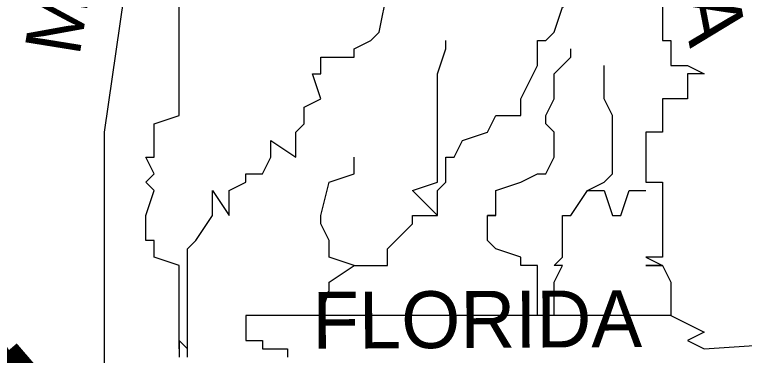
# Model space of a CAD drawing. Extents: x -12822 to 16384, y -6351 to 1913.
# Drawn here: x 65.86 to 88.88, y -4811.36 to -4800.61 of the extents above; entities that cross this region are included whole.
import ezdxf

# ---------------------------------------------------------------- set-up
doc = ezdxf.new("R2010")
doc.units = 0
doc.layers.add('great seal', color=7, linetype='Continuous')

msp = doc.modelspace()

# ---------------------------------------------------------------- linework, layer by layer
at = {"layer": 'great seal'}
for points in [[(68.693, -4813.516), (68.693, -4804.319), (71.058, -4788.028)], [(68.693, -4813.516), (68.693, -4804.319), (71.058, -4788.028)], [(68.693, -4813.516), (68.693, -4804.319), (71.058, -4788.028)], [(79.204, -4806.947), (79.204, -4806.947), (79.204, -4806.159), (79.467, -4805.896), (79.467, -4805.633), (79.467, -4805.107), (79.729, -4805.107), (79.992, -4804.582), (80.78, -4804.319), (81.043, -4803.794), (81.832, -4803.794), (81.832, -4803.268), (82.357, -4802.217), (82.357, -4801.692), (82.357, -4801.692), (82.357, -4801.429), (82.62, -4801.429), (82.883, -4801.166), (83.145, -4800.378), (83.934, -4799.852), (84.459, -4799.589), (84.459, -4799.327), (84.459, -4799.064), (83.934, -4799.064)], [(79.204, -4806.947), (79.204, -4806.947), (79.204, -4806.159), (79.467, -4805.896), (79.467, -4805.633), (79.467, -4805.107), (79.729, -4805.107), (79.992, -4804.582), (80.78, -4804.319), (81.043, -4803.794), (81.832, -4803.794), (81.832, -4803.268), (82.357, -4802.217), (82.357, -4801.692), (82.357, -4801.692), (82.357, -4801.429), (82.62, -4801.429), (82.883, -4801.166), (83.145, -4800.378), (83.934, -4799.852), (84.459, -4799.589), (84.459, -4799.327), (84.459, -4799.064), (83.934, -4799.064)], [(79.204, -4806.947), (79.204, -4806.947), (79.204, -4806.159), (79.467, -4805.896), (79.467, -4805.633), (79.467, -4805.107), (79.729, -4805.107), (79.992, -4804.582), (80.78, -4804.319), (81.043, -4803.794), (81.832, -4803.794), (81.832, -4803.268), (82.357, -4802.217), (82.357, -4801.692), (82.357, -4801.692), (82.357, -4801.429), (82.62, -4801.429), (82.883, -4801.166), (83.145, -4800.378), (83.934, -4799.852), (84.459, -4799.589), (84.459, -4799.327), (84.459, -4799.064), (83.934, -4799.064)], [(71.321, -4811.151), (71.321, -4810.888), (71.321, -4810.363), (71.321, -4810.363), (71.321, -4809.312), (71.321, -4809.049), (71.321, -4808.523), (71.321, -4808.523), (71.321, -4808.261), (71.321, -4807.998), (71.584, -4807.735), (72.109, -4806.947), (72.109, -4806.159), (72.635, -4806.947), (72.635, -4806.159), (73.16, -4805.896), (73.16, -4805.633), (73.686, -4805.633), (73.949, -4805.107), (73.949, -4804.582), (74.737, -4805.107), (74.737, -4804.319), (75, -4804.056), (75, -4803.794), (75, -4803.531), (75.525, -4803.268), (75.262, -4802.48), (75.525, -4802.48), (75.525, -4801.954), (76.576, -4801.954), (76.576, -4801.692), (76.576, -4801.692), (77.102, -4801.429), (77.365, -4801.166), (77.627, -4799.852)], [(71.321, -4811.151), (71.321, -4810.888), (71.321, -4810.363), (71.321, -4810.363), (71.321, -4809.312), (71.321, -4809.049), (71.321, -4808.523), (71.321, -4808.523), (71.321, -4808.261), (71.321, -4807.998), (71.584, -4807.735), (72.109, -4806.947), (72.109, -4806.159), (72.635, -4806.947), (72.635, -4806.159), (73.16, -4805.896), (73.16, -4805.633), (73.686, -4805.633), (73.949, -4805.107), (73.949, -4804.582), (74.737, -4805.107), (74.737, -4804.319), (75, -4804.056), (75, -4803.794), (75, -4803.531), (75.525, -4803.268), (75.262, -4802.48), (75.525, -4802.48), (75.525, -4801.954), (76.576, -4801.954), (76.576, -4801.692), (76.576, -4801.692), (77.102, -4801.429), (77.365, -4801.166), (77.627, -4799.852)], [(71.321, -4811.151), (71.321, -4810.888), (71.321, -4810.363), (71.321, -4810.363), (71.321, -4809.312), (71.321, -4809.049), (71.321, -4808.523), (71.321, -4808.523), (71.321, -4808.261), (71.321, -4807.998), (71.584, -4807.735), (72.109, -4806.947), (72.109, -4806.159), (72.635, -4806.947), (72.635, -4806.159), (73.16, -4805.896), (73.16, -4805.633), (73.686, -4805.633), (73.949, -4805.107), (73.949, -4804.582), (74.737, -4805.107), (74.737, -4804.319), (75, -4804.056), (75, -4803.794), (75, -4803.531), (75.525, -4803.268), (75.262, -4802.48), (75.525, -4802.48), (75.525, -4801.954), (76.576, -4801.954), (76.576, -4801.692), (76.576, -4801.692), (77.102, -4801.429), (77.365, -4801.166), (77.627, -4799.852)], [(71.058, -4811.151), (71.058, -4810.888), (71.058, -4810.363), (71.058, -4810.363), (71.058, -4810.1), (71.058, -4810.1), (71.058, -4809.049), (71.058, -4808.523), (71.058, -4808.523), (70.27, -4808.261), (70.27, -4807.998), (70.27, -4807.735), (70.007, -4807.735), (70.007, -4806.947), (70.007, -4806.947), (70.27, -4806.159), (70.007, -4805.896), (70.27, -4805.633), (70.007, -4805.107), (70.007, -4805.107), (70.007, -4805.107), (70.27, -4805.107), (70.27, -4804.319), (70.27, -4804.319), (70.27, -4804.056), (71.058, -4803.794), (71.058, -4803.531), (71.058, -4803.268), (71.058, -4802.48), (71.058, -4802.217), (71.058, -4801.692), (71.058, -4801.692), (71.058, -4801.429), (71.058, -4800.378)], [(71.058, -4811.151), (71.058, -4810.888), (71.058, -4810.363), (71.058, -4810.363), (71.058, -4810.1), (71.058, -4810.1), (71.058, -4809.049), (71.058, -4808.523), (71.058, -4808.523), (70.27, -4808.261), (70.27, -4807.998), (70.27, -4807.735), (70.007, -4807.735), (70.007, -4806.947), (70.007, -4806.947), (70.27, -4806.159), (70.007, -4805.896), (70.27, -4805.633), (70.007, -4805.107), (70.007, -4805.107), (70.007, -4805.107), (70.27, -4805.107), (70.27, -4804.319), (70.27, -4804.319), (70.27, -4804.056), (71.058, -4803.794), (71.058, -4803.531), (71.058, -4803.268), (71.058, -4802.48), (71.058, -4802.217), (71.058, -4801.692), (71.058, -4801.692), (71.058, -4801.429), (71.058, -4800.378)], [(71.058, -4811.151), (71.058, -4810.888), (71.058, -4810.363), (71.058, -4810.363), (71.058, -4810.1), (71.058, -4810.1), (71.058, -4809.049), (71.058, -4808.523), (71.058, -4808.523), (70.27, -4808.261), (70.27, -4807.998), (70.27, -4807.735), (70.007, -4807.735), (70.007, -4806.947), (70.007, -4806.947), (70.27, -4806.159), (70.007, -4805.896), (70.27, -4805.633), (70.007, -4805.107), (70.007, -4805.107), (70.007, -4805.107), (70.27, -4805.107), (70.27, -4804.319), (70.27, -4804.319), (70.27, -4804.056), (71.058, -4803.794), (71.058, -4803.531), (71.058, -4803.268), (71.058, -4802.48), (71.058, -4802.217), (71.058, -4801.692), (71.058, -4801.692), (71.058, -4801.429), (71.058, -4800.378)], [(86.299, -4800.378), (86.299, -4801.166), (86.299, -4801.429), (86.561, -4801.429), (86.561, -4801.692), (86.561, -4801.692), (86.561, -4801.954), (86.561, -4802.217), (87.087, -4802.217), (87.612, -4802.48), (87.087, -4802.48), (87.087, -4803.268), (87.087, -4803.268), (86.561, -4803.268), (86.561, -4803.268), (86.561, -4803.268), (86.561, -4803.268), (86.299, -4803.268), (86.299, -4803.268), (86.299, -4803.268), (86.299, -4803.531), (86.299, -4803.794), (86.299, -4803.794), (86.299, -4803.794), (86.299, -4803.794), (86.299, -4803.794), (86.299, -4804.056), (86.299, -4804.056), (86.299, -4804.056), (86.299, -4804.319), (86.299, -4804.319), (85.773, -4804.319), (85.773, -4804.319), (85.773, -4804.319), (85.773, -4804.582), (85.773, -4804.582), (85.773, -4805.107), (85.773, -4805.107), (85.773, -4805.107), (85.773, -4805.107), (85.773, -4805.107), (85.773, -4805.107), (85.773, -4805.107), (85.773, -4805.633), (85.773, -4805.633), (85.773, -4805.633), (85.773, -4805.633), (85.773, -4805.633), (85.773, -4805.633), (85.773, -4805.896), (86.299, -4805.896), (86.299, -4806.159), (86.299, -4806.159), (86.299, -4806.159), (86.299, -4806.947), (86.299, -4806.947), (86.299, -4806.947), (86.299, -4806.947), (86.299, -4806.947), (86.299, -4806.947), (86.299, -4807.21), (86.299, -4807.735), (86.299, -4807.735), (86.299, -4807.735), (86.299, -4807.998), (86.299, -4807.998), (86.299, -4808.261), (86.299, -4808.261), (85.773, -4808.261), (85.773, -4808.261), (85.773, -4808.261), (85.773, -4808.261), (86.299, -4808.523), (86.299, -4808.523), (85.773, -4808.523), (86.299, -4808.523), (86.299, -4808.523), (86.299, -4808.523), (86.561, -4809.049), (86.561, -4809.049), (86.561, -4809.312), (86.561, -4809.312), (86.561, -4810.1), (73.16, -4810.1), (73.16, -4810.363), (73.16, -4810.363)], [(86.299, -4800.378), (86.299, -4801.166), (86.299, -4801.429), (86.561, -4801.429), (86.561, -4801.692), (86.561, -4801.692), (86.561, -4801.954), (86.561, -4802.217), (87.087, -4802.217), (87.612, -4802.48), (87.087, -4802.48), (87.087, -4803.268), (87.087, -4803.268), (86.561, -4803.268), (86.561, -4803.268), (86.561, -4803.268), (86.561, -4803.268), (86.299, -4803.268), (86.299, -4803.268), (86.299, -4803.268), (86.299, -4803.531), (86.299, -4803.794), (86.299, -4803.794), (86.299, -4803.794), (86.299, -4803.794), (86.299, -4803.794), (86.299, -4804.056), (86.299, -4804.056), (86.299, -4804.056), (86.299, -4804.319), (86.299, -4804.319), (85.773, -4804.319), (85.773, -4804.319), (85.773, -4804.319), (85.773, -4804.582), (85.773, -4804.582), (85.773, -4805.107), (85.773, -4805.107), (85.773, -4805.107), (85.773, -4805.107), (85.773, -4805.107), (85.773, -4805.107), (85.773, -4805.107), (85.773, -4805.633), (85.773, -4805.633), (85.773, -4805.633), (85.773, -4805.633), (85.773, -4805.633), (85.773, -4805.633), (85.773, -4805.896), (86.299, -4805.896), (86.299, -4806.159), (86.299, -4806.159), (86.299, -4806.159), (86.299, -4806.947), (86.299, -4806.947), (86.299, -4806.947), (86.299, -4806.947), (86.299, -4806.947), (86.299, -4806.947), (86.299, -4807.21), (86.299, -4807.735), (86.299, -4807.735), (86.299, -4807.735), (86.299, -4807.998), (86.299, -4807.998), (86.299, -4808.261), (86.299, -4808.261), (85.773, -4808.261), (85.773, -4808.261), (85.773, -4808.261), (85.773, -4808.261), (86.299, -4808.523), (86.299, -4808.523), (85.773, -4808.523), (86.299, -4808.523), (86.299, -4808.523), (86.299, -4808.523), (86.561, -4809.049), (86.561, -4809.049), (86.561, -4809.312), (86.561, -4809.312), (86.561, -4810.1), (73.16, -4810.1), (73.16, -4810.363), (73.16, -4810.363)], [(86.299, -4800.378), (86.299, -4801.166), (86.299, -4801.429), (86.561, -4801.429), (86.561, -4801.692), (86.561, -4801.692), (86.561, -4801.954), (86.561, -4802.217), (87.087, -4802.217), (87.612, -4802.48), (87.087, -4802.48), (87.087, -4803.268), (87.087, -4803.268), (86.561, -4803.268), (86.561, -4803.268), (86.561, -4803.268), (86.561, -4803.268), (86.299, -4803.268), (86.299, -4803.268), (86.299, -4803.268), (86.299, -4803.531), (86.299, -4803.794), (86.299, -4803.794), (86.299, -4803.794), (86.299, -4803.794), (86.299, -4803.794), (86.299, -4804.056), (86.299, -4804.056), (86.299, -4804.056), (86.299, -4804.319), (86.299, -4804.319), (85.773, -4804.319), (85.773, -4804.319), (85.773, -4804.319), (85.773, -4804.582), (85.773, -4804.582), (85.773, -4805.107), (85.773, -4805.107), (85.773, -4805.107), (85.773, -4805.107), (85.773, -4805.107), (85.773, -4805.107), (85.773, -4805.107), (85.773, -4805.633), (85.773, -4805.633), (85.773, -4805.633), (85.773, -4805.633), (85.773, -4805.633), (85.773, -4805.633), (85.773, -4805.896), (86.299, -4805.896), (86.299, -4806.159), (86.299, -4806.159), (86.299, -4806.159), (86.299, -4806.947), (86.299, -4806.947), (86.299, -4806.947), (86.299, -4806.947), (86.299, -4806.947), (86.299, -4806.947), (86.299, -4807.21), (86.299, -4807.735), (86.299, -4807.735), (86.299, -4807.735), (86.299, -4807.998), (86.299, -4807.998), (86.299, -4808.261), (86.299, -4808.261), (85.773, -4808.261), (85.773, -4808.261), (85.773, -4808.261), (85.773, -4808.261), (86.299, -4808.523), (86.299, -4808.523), (85.773, -4808.523), (86.299, -4808.523), (86.299, -4808.523), (86.299, -4808.523), (86.561, -4809.049), (86.561, -4809.049), (86.561, -4809.312), (86.561, -4809.312), (86.561, -4810.1), (73.16, -4810.1), (73.16, -4810.363), (73.16, -4810.363)], [(76.576, -4808.523), (76.576, -4808.523), (77.102, -4808.523), (77.365, -4808.523), (77.627, -4808.523), (77.627, -4808.261), (77.627, -4807.998), (77.89, -4807.735), (78.416, -4807.21), (78.416, -4806.947), (79.204, -4806.947), (79.204, -4806.947), (78.416, -4806.159), (79.204, -4805.896), (79.204, -4805.633), (79.204, -4805.107), (79.204, -4804.582), (79.204, -4804.319), (79.204, -4803.794), (79.204, -4803.794), (79.204, -4803.268), (79.204, -4802.48), (79.467, -4801.692), (79.467, -4801.692), (79.467, -4801.429)], [(76.576, -4808.523), (76.576, -4808.523), (77.102, -4808.523), (77.365, -4808.523), (77.627, -4808.523), (77.627, -4808.261), (77.627, -4807.998), (77.89, -4807.735), (78.416, -4807.21), (78.416, -4806.947), (79.204, -4806.947), (79.204, -4806.947), (78.416, -4806.159), (79.204, -4805.896), (79.204, -4805.633), (79.204, -4805.107), (79.204, -4804.582), (79.204, -4804.319), (79.204, -4803.794), (79.204, -4803.794), (79.204, -4803.268), (79.204, -4802.48), (79.467, -4801.692), (79.467, -4801.692), (79.467, -4801.429)], [(76.576, -4808.523), (76.576, -4808.523), (77.102, -4808.523), (77.365, -4808.523), (77.627, -4808.523), (77.627, -4808.261), (77.627, -4807.998), (77.89, -4807.735), (78.416, -4807.21), (78.416, -4806.947), (79.204, -4806.947), (79.204, -4806.947), (78.416, -4806.159), (79.204, -4805.896), (79.204, -4805.633), (79.204, -4805.107), (79.204, -4804.582), (79.204, -4804.319), (79.204, -4803.794), (79.204, -4803.794), (79.204, -4803.268), (79.204, -4802.48), (79.467, -4801.692), (79.467, -4801.692), (79.467, -4801.429)], [(82.357, -4810.1), (82.357, -4809.312), (82.357, -4809.049), (82.357, -4808.523), (82.357, -4808.523), (81.832, -4808.523), (81.832, -4808.261), (81.043, -4807.998), (80.78, -4807.735), (80.78, -4807.21), (80.78, -4806.947), (81.043, -4806.947), (80.78, -4806.947), (81.043, -4806.947), (81.043, -4806.159), (81.832, -4805.896), (82.357, -4805.633), (82.357, -4805.633), (82.62, -4805.633), (82.883, -4805.107), (82.883, -4805.107), (82.883, -4804.582), (82.883, -4804.319), (82.883, -4804.319), (82.62, -4804.056), (82.62, -4803.794), (82.883, -4803.268), (82.883, -4802.48), (83.145, -4802.217), (83.408, -4801.954), (83.408, -4801.692)], [(82.357, -4810.1), (82.357, -4809.312), (82.357, -4809.049), (82.357, -4808.523), (82.357, -4808.523), (81.832, -4808.523), (81.832, -4808.261), (81.043, -4807.998), (80.78, -4807.735), (80.78, -4807.21), (80.78, -4806.947), (81.043, -4806.947), (80.78, -4806.947), (81.043, -4806.947), (81.043, -4806.159), (81.832, -4805.896), (82.357, -4805.633), (82.357, -4805.633), (82.62, -4805.633), (82.883, -4805.107), (82.883, -4805.107), (82.883, -4804.582), (82.883, -4804.319), (82.883, -4804.319), (82.62, -4804.056), (82.62, -4803.794), (82.883, -4803.268), (82.883, -4802.48), (83.145, -4802.217), (83.408, -4801.954), (83.408, -4801.692)], [(82.357, -4810.1), (82.357, -4809.312), (82.357, -4809.049), (82.357, -4808.523), (82.357, -4808.523), (81.832, -4808.523), (81.832, -4808.261), (81.043, -4807.998), (80.78, -4807.735), (80.78, -4807.21), (80.78, -4806.947), (81.043, -4806.947), (80.78, -4806.947), (81.043, -4806.947), (81.043, -4806.159), (81.832, -4805.896), (82.357, -4805.633), (82.357, -4805.633), (82.62, -4805.633), (82.883, -4805.107), (82.883, -4805.107), (82.883, -4804.582), (82.883, -4804.319), (82.883, -4804.319), (82.62, -4804.056), (82.62, -4803.794), (82.883, -4803.268), (82.883, -4802.48), (83.145, -4802.217), (83.408, -4801.954), (83.408, -4801.692)], [(83.934, -4806.159), (83.934, -4806.159), (84.459, -4805.896), (84.722, -4805.633), (84.722, -4805.633), (84.722, -4805.107), (84.722, -4804.582), (84.722, -4804.319), (84.722, -4804.056), (84.722, -4803.794), (84.459, -4803.268), (84.459, -4803.268), (84.459, -4802.217)], [(83.934, -4806.159), (83.934, -4806.159), (84.459, -4805.896), (84.722, -4805.633), (84.722, -4805.633), (84.722, -4805.107), (84.722, -4804.582), (84.722, -4804.319), (84.722, -4804.056), (84.722, -4803.794), (84.459, -4803.268), (84.459, -4803.268), (84.459, -4802.217)], [(83.934, -4806.159), (83.934, -4806.159), (84.459, -4805.896), (84.722, -4805.633), (84.722, -4805.633), (84.722, -4805.107), (84.722, -4804.582), (84.722, -4804.319), (84.722, -4804.056), (84.722, -4803.794), (84.459, -4803.268), (84.459, -4803.268), (84.459, -4802.217)], [(75.525, -4810.1), (75.788, -4809.312), (75.788, -4809.049), (76.576, -4808.523), (76.576, -4808.523), (76.576, -4808.523), (75.788, -4808.261), (75.788, -4807.998), (75.788, -4807.735), (75.525, -4807.21), (75.525, -4806.947), (75.525, -4806.947), (75.788, -4805.896), (76.576, -4805.633), (76.576, -4805.107)], [(75.525, -4810.1), (75.788, -4809.312), (75.788, -4809.049), (76.576, -4808.523), (76.576, -4808.523), (76.576, -4808.523), (75.788, -4808.261), (75.788, -4807.998), (75.788, -4807.735), (75.525, -4807.21), (75.525, -4806.947), (75.525, -4806.947), (75.788, -4805.896), (76.576, -4805.633), (76.576, -4805.107)], [(75.525, -4810.1), (75.788, -4809.312), (75.788, -4809.049), (76.576, -4808.523), (76.576, -4808.523), (76.576, -4808.523), (75.788, -4808.261), (75.788, -4807.998), (75.788, -4807.735), (75.525, -4807.21), (75.525, -4806.947), (75.525, -4806.947), (75.788, -4805.896), (76.576, -4805.633), (76.576, -4805.107)], [(82.883, -4810.1), (82.883, -4809.312), (82.883, -4809.312), (82.883, -4809.049), (83.145, -4808.523), (82.883, -4808.523), (83.145, -4808.261), (83.145, -4807.998), (83.145, -4807.735), (83.145, -4807.735), (83.145, -4807.21), (83.145, -4806.947), (83.408, -4806.947), (83.934, -4806.159), (84.459, -4806.159), (84.722, -4806.947), (84.985, -4806.947), (85.247, -4806.159), (85.51, -4806.159), (85.773, -4806.159)], [(82.883, -4810.1), (82.883, -4809.312), (82.883, -4809.312), (82.883, -4809.049), (83.145, -4808.523), (82.883, -4808.523), (83.145, -4808.261), (83.145, -4807.998), (83.145, -4807.735), (83.145, -4807.735), (83.145, -4807.21), (83.145, -4806.947), (83.408, -4806.947), (83.934, -4806.159), (84.459, -4806.159), (84.722, -4806.947), (84.985, -4806.947), (85.247, -4806.159), (85.51, -4806.159), (85.773, -4806.159)], [(82.883, -4810.1), (82.883, -4809.312), (82.883, -4809.312), (82.883, -4809.049), (83.145, -4808.523), (82.883, -4808.523), (83.145, -4808.261), (83.145, -4807.998), (83.145, -4807.735), (83.145, -4807.735), (83.145, -4807.21), (83.145, -4806.947), (83.408, -4806.947), (83.934, -4806.159), (84.459, -4806.159), (84.722, -4806.947), (84.985, -4806.947), (85.247, -4806.159), (85.51, -4806.159), (85.773, -4806.159)], [(86.561, -4810.1), (87.087, -4810.363), (87.087, -4810.363), (87.612, -4810.626), (87.087, -4810.888), (87.612, -4811.151), (91.554, -4810.888)], [(86.561, -4810.1), (87.087, -4810.363), (87.087, -4810.363), (87.612, -4810.626), (87.087, -4810.888), (87.612, -4811.151), (91.554, -4810.888)], [(86.561, -4810.1), (87.087, -4810.363), (87.087, -4810.363), (87.612, -4810.626), (87.087, -4810.888), (87.612, -4811.151), (91.554, -4810.888)], [(73.16, -4810.363), (73.16, -4810.626), (73.16, -4810.626), (73.16, -4810.888), (73.16, -4810.888), (73.686, -4810.888), (73.686, -4810.888), (73.686, -4811.151), (73.949, -4811.151), (73.949, -4811.151), (73.949, -4811.151), (74.474, -4811.151), (74.474, -4811.151), (74.474, -4811.151), (74.474, -4811.414)], [(73.16, -4810.363), (73.16, -4810.626), (73.16, -4810.626), (73.16, -4810.888), (73.16, -4810.888), (73.686, -4810.888), (73.686, -4810.888), (73.686, -4811.151), (73.949, -4811.151), (73.949, -4811.151), (73.949, -4811.151), (74.474, -4811.151), (74.474, -4811.151), (74.474, -4811.151), (74.474, -4811.414)], [(73.16, -4810.363), (73.16, -4810.626), (73.16, -4810.626), (73.16, -4810.888), (73.16, -4810.888), (73.686, -4810.888), (73.686, -4810.888), (73.686, -4811.151), (73.949, -4811.151), (73.949, -4811.151), (73.949, -4811.151), (74.474, -4811.151), (74.474, -4811.151), (74.474, -4811.151), (74.474, -4811.414)], [(71.321, -4811.414), (71.321, -4811.151), (71.321, -4811.151), (71.321, -4811.151), (71.321, -4811.151), (71.321, -4811.151), (71.321, -4811.151), (71.321, -4811.151), (71.058, -4810.888)], [(71.058, -4810.888), (71.058, -4810.888), (71.058, -4811.151), (71.058, -4811.151), (71.058, -4811.151), (71.058, -4811.151), (71.058, -4811.151), (71.058, -4811.151), (71.058, -4811.414)], [(71.321, -4811.414), (71.321, -4811.151), (71.321, -4811.151), (71.321, -4811.151), (71.321, -4811.151), (71.321, -4811.151), (71.321, -4811.151), (71.321, -4811.151), (71.058, -4810.888)], [(71.058, -4810.888), (71.058, -4810.888), (71.058, -4811.151), (71.058, -4811.151), (71.058, -4811.151), (71.058, -4811.151), (71.058, -4811.151), (71.058, -4811.151), (71.058, -4811.414)], [(71.321, -4811.414), (71.321, -4811.151), (71.321, -4811.151), (71.321, -4811.151), (71.321, -4811.151), (71.321, -4811.151), (71.321, -4811.151), (71.321, -4811.151), (71.058, -4810.888)], [(71.058, -4810.888), (71.058, -4810.888), (71.058, -4811.151), (71.058, -4811.151), (71.058, -4811.151), (71.058, -4811.151), (71.058, -4811.151), (71.058, -4811.151), (71.058, -4811.414)], [(71.321, -4811.151), (71.321, -4811.151)], [(71.321, -4811.151), (71.321, -4811.151)], [(71.321, -4811.151), (71.321, -4811.151)]]:
    msp.add_lwpolyline(points, dxfattribs=at)
for radius in [22.994, 22.994, 22.994, 22.389, 22.389, 22.389, 17.779, 17.779, 17.779, 17.222, 17.222, 17.222]:
    msp.add_circle((77.645, -4800.299), radius, dxfattribs=at)

# ---------------------------------------------------------------- texts
for s, height, rotation, p in [('MISSISSIPPI', 1.75474, 80.8531, (67.905, -4801.954)), ('MISSISSIPPI', 1.75474, 80.8531, (67.905, -4801.954)), ('MISSISSIPPI', 1.75474, 80.8531, (67.905, -4801.954)), ('GEORGIA', 1.8446, 280.9296, (84.985, -4790.393)), ('GEORGIA', 1.8446, 280.9296, (84.985, -4790.393)), ('GEORGIA', 1.8446, 280.9296, (84.985, -4790.393)), ('FLORIDA', 1.7941, 0.3238, (75.262, -4811.151)), ('FLORIDA', 1.7941, 0.3238, (75.262, -4811.151)), ('FLORIDA', 1.7941, 0.3238, (75.262, -4811.151)), ('E', 5.851, 302.3539, (59.234, -4811.939)), ('E', 5.851, 302.3539, (59.234, -4811.939)), ('E', 5.851, 302.3539, (59.234, -4811.939)), ('N', 5.851, 310.6423, (61.073, -4814.304)), ('N', 5.851, 310.6423, (61.073, -4814.304)), ('N', 5.851, 310.6423, (61.073, -4814.304))]:
    msp.add_text(s, height=height, rotation=rotation, dxfattribs=at).set_placement(p)

doc.saveas('drawing.dxf')
